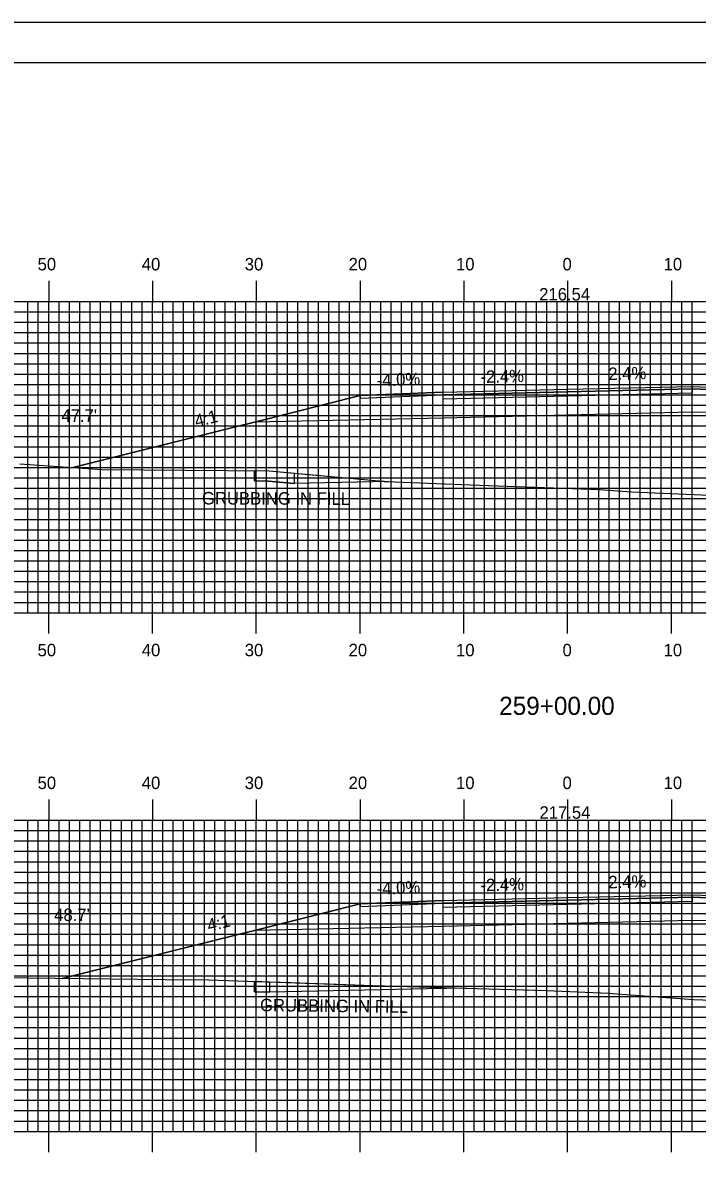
# Model space of a CAD drawing. Extents: x 1805471 to 1805814, y 442591 to 442811.
# Drawn here: x 1805584.2 to 1805649.2, y 442701.2 to 442810.5 of the extents above; entities that cross this region are included whole.
import ezdxf

# ---------------------------------------------------------------- set-up
doc = ezdxf.new("R2010")
doc.units = 0
for name, color, linetype in [('ANNOTATION', 7, 'Continuous'), ('BORDER', 7, 'Continuous'), ('D_Roadway_Centerline', 7, 'Continuous'), ('D_Roadway_Centerline_Text', 7, 'Continuous'), ('D_Roadway_Edge_Shoulder', 7, 'Continuous'), ('D_Roadway_Edge_TW', 7, 'Continuous'), ('D_Roadway_Pavement', 7, 'Continuous'), ('D_Roadway_SlopeLines', 7, 'Continuous'), ('D_Roadway_SubGrade', 7, 'Continuous'), ('D_Text_Standard', 7, 'Continuous'), ('GRUBBING IN FILL', 7, 'Continuous'), ('H_V ANNOTATION', 7, 'Continuous'), ('MAJOR', 7, 'Continuous'), ('MINOR', 7, 'Continuous'), ('PLOT BOUNDARY', 7, 'Continuous'), ('S_Roadway_Centerline', 7, 'Continuous')]:
    doc.layers.add(name, color=color, linetype=linetype)

msp = doc.modelspace()

# ---------------------------------------------------------------- linework, layer by layer
at = {"layer": 'BORDER'}
msp.add_lwpolyline([(1805487.11, 442596.67), (1805807.11, 442596.67), (1805807.11, 442806.67), (1805487.11, 442806.67)], close=True, dxfattribs=at)
at = {"layer": 'D_Roadway_Centerline'}
for points in [[(1805589.04, 442767.68), (1805604.71, 442771.6), (1805606.53, 442772.05), (1805616.71, 442774.6), (1805624.71, 442774.92), (1805636.71, 442775.21), (1805648.71, 442775.49), (1805656.71, 442775.17), (1805666.88, 442772.63), (1805668.71, 442772.17), (1805696.54, 442762.9)], [(1805588.01, 442718.42), (1805604.71, 442722.6), (1805606.53, 442723.05), (1805616.71, 442725.6), (1805624.71, 442725.92), (1805636.71, 442726.21), (1805648.71, 442726.49), (1805656.71, 442726.17), (1805666.88, 442723.63), (1805668.71, 442723.17), (1805693.01, 442715.07)]]:
    msp.add_lwpolyline(points, dxfattribs=at)
at = {"layer": 'D_Roadway_Edge_Shoulder'}
for points in [[(1805648.71, 442775.49), (1805656.71, 442775.17), (1805656.71, 442774.92), (1805648.71, 442775.24)], [(1805624.71, 442774.92), (1805616.71, 442774.6), (1805616.71, 442774.35), (1805624.71, 442774.67)], [(1805648.71, 442726.49), (1805656.71, 442726.17), (1805656.71, 442725.92), (1805648.71, 442726.24)], [(1805624.71, 442725.92), (1805616.71, 442725.6), (1805616.71, 442725.35), (1805624.71, 442725.67)]]:
    msp.add_lwpolyline(points, close=True, dxfattribs=at)
at = {"layer": 'D_Roadway_Edge_TW'}
for points in [[(1805624.71, 442774.67), (1805624.71, 442774.92), (1805636.71, 442775.21), (1805648.71, 442775.49), (1805648.71, 442775.24), (1805636.71, 442774.96)], [(1805624.71, 442725.67), (1805624.71, 442725.92), (1805636.71, 442726.21), (1805648.71, 442726.49), (1805648.71, 442726.24), (1805636.71, 442725.96)]]:
    msp.add_lwpolyline(points, close=True, dxfattribs=at)
at = {"layer": 'D_Roadway_Pavement'}
for points in [[(1805624.71, 442774.25), (1805624.71, 442774.67), (1805636.71, 442774.96), (1805648.71, 442775.24), (1805648.71, 442774.83), (1805636.71, 442774.54)], [(1805624.71, 442725.25), (1805624.71, 442725.67), (1805636.71, 442725.96), (1805648.71, 442726.24), (1805648.71, 442725.83), (1805636.71, 442725.54)]]:
    msp.add_lwpolyline(points, close=True, dxfattribs=at)
at = {"layer": 'D_Roadway_SlopeLines'}
for points in [[(1805616.71, 442774.6), (1805606.53, 442772.05), (1805604.71, 442771.6), (1805589.04, 442767.68)], [(1805616.71, 442725.6), (1805606.53, 442723.05), (1805604.71, 442722.6), (1805588.01, 442718.42)]]:
    msp.add_lwpolyline(points, dxfattribs=at)
at = {"layer": 'D_Roadway_SubGrade'}
for points in [[(1805624.71, 442772.42), (1805606.53, 442772.05), (1805616.71, 442774.6), (1805616.71, 442774.35), (1805624.71, 442774.67), (1805636.71, 442774.96), (1805648.71, 442775.24), (1805656.71, 442774.92), (1805656.71, 442775.17), (1805666.88, 442772.63), (1805648.71, 442772.99), (1805636.71, 442772.71)], [(1805624.71, 442723.42), (1805606.53, 442723.05), (1805616.71, 442725.6), (1805616.71, 442725.35), (1805624.71, 442725.67), (1805636.71, 442725.96), (1805648.71, 442726.24), (1805656.71, 442725.92), (1805656.71, 442726.17), (1805666.88, 442723.63), (1805648.71, 442723.99), (1805636.71, 442723.71)]]:
    msp.add_lwpolyline(points, close=True, dxfattribs=at)
at = {"layer": 'GRUBBING IN FILL'}
for p, q in [((1805606.53, 442767.37), (1805606.53, 442766.37)), ((1805606.53, 442767.37), (1805606.53, 442766.37)), ((1805610.37, 442767.13), (1805610.37, 442766.13)), ((1805610.37, 442767.13), (1805610.37, 442766.13)), ((1805606.53, 442718.14), (1805606.53, 442717.14)), ((1805606.53, 442718.14), (1805606.53, 442717.14)), ((1805608, 442718.08), (1805608, 442717.08)), ((1805608, 442718.08), (1805608, 442717.08))]:
    msp.add_line(p, q, dxfattribs=at)
for points in [[(1805606.53, 442767.37), (1805607.94, 442767.36), (1805610.37, 442767.13), (1805618.17, 442766.41), (1805619.44, 442766.31), (1805610.37, 442766.13), (1805607.89, 442766.36), (1805606.53, 442766.37)], [(1805606.53, 442767.37), (1805607.94, 442767.36), (1805610.37, 442767.13), (1805618.17, 442766.41), (1805619.44, 442766.31), (1805610.37, 442766.13), (1805607.89, 442766.36), (1805606.53, 442766.37)], [(1805606.53, 442718.14), (1805608, 442718.08), (1805610.05, 442718.01), (1805617.95, 442717.73), (1805626.94, 442717.48), (1805623.18, 442717.4), (1805615.64, 442717.24), (1805611.1, 442717.15), (1805608, 442717.08), (1805606.53, 442717.13)], [(1805606.53, 442718.14), (1805608, 442718.08), (1805610.05, 442718.01), (1805617.95, 442717.73), (1805626.94, 442717.48), (1805623.18, 442717.4), (1805615.64, 442717.24), (1805611.1, 442717.15), (1805608, 442717.08), (1805606.53, 442717.13)]]:
    msp.add_lwpolyline(points, close=True, dxfattribs=at)
for points in [[(1805606.53, 442766.37), (1805607.89, 442766.36), (1805610.37, 442766.13)], [(1805606.53, 442766.37), (1805607.89, 442766.36), (1805610.37, 442766.13)], [(1805606.53, 442717.13), (1805607.99, 442717.08)], [(1805606.53, 442717.13), (1805607.99, 442717.08)]]:
    msp.add_lwpolyline(points, dxfattribs=at)
at = {"layer": 'MAJOR'}
for p, q in [((1805586.71, 442785.67), (1805586.71, 442783.67)), ((1805596.71, 442785.67), (1805596.71, 442783.67)), ((1805606.71, 442785.67), (1805606.71, 442783.67)), ((1805616.71, 442785.67), (1805616.71, 442783.67)), ((1805626.71, 442785.67), (1805626.71, 442783.67)), ((1805636.71, 442785.67), (1805636.71, 442783.67)), ((1805646.71, 442785.67), (1805646.71, 442783.67)), ((1805496.71, 442783.67), (1805776.71, 442783.67)), ((1805496.71, 442783.67), (1805776.71, 442783.67)), ((1805586.71, 442753.67), (1805586.71, 442783.67)), ((1805596.71, 442753.67), (1805596.71, 442783.67)), ((1805606.71, 442753.67), (1805606.71, 442783.67)), ((1805616.71, 442753.67), (1805616.71, 442783.67)), ((1805626.71, 442753.67), (1805626.71, 442783.67)), ((1805636.71, 442753.67), (1805636.71, 442783.67)), ((1805646.71, 442753.67), (1805646.71, 442783.67)), ((1805496.71, 442778.67), (1805776.71, 442778.67)), ((1805496.71, 442773.67), (1805776.71, 442773.67)), ((1805496.71, 442768.67), (1805776.71, 442768.67)), ((1805496.71, 442763.67), (1805776.71, 442763.67)), ((1805496.71, 442758.67), (1805776.71, 442758.67)), ((1805496.71, 442753.67), (1805776.71, 442753.67)), ((1805496.71, 442753.67), (1805776.71, 442753.67)), ((1805586.71, 442751.66), (1805586.71, 442753.67)), ((1805596.71, 442751.66), (1805596.71, 442753.67)), ((1805606.71, 442751.66), (1805606.71, 442753.67)), ((1805616.71, 442751.66), (1805616.71, 442753.67)), ((1805626.71, 442751.66), (1805626.71, 442753.67)), ((1805636.71, 442751.66), (1805636.71, 442753.67)), ((1805646.71, 442751.66), (1805646.71, 442753.67)), ((1805586.71, 442735.67), (1805586.71, 442733.67)), ((1805596.71, 442735.67), (1805596.71, 442733.67)), ((1805606.71, 442735.67), (1805606.71, 442733.67)), ((1805616.71, 442735.67), (1805616.71, 442733.67)), ((1805626.71, 442735.67), (1805626.71, 442733.67)), ((1805636.71, 442735.67), (1805636.71, 442733.67)), ((1805646.71, 442735.67), (1805646.71, 442733.67)), ((1805496.71, 442733.67), (1805776.71, 442733.67)), ((1805496.71, 442733.67), (1805776.71, 442733.67)), ((1805586.71, 442703.67), (1805586.71, 442733.67)), ((1805596.71, 442703.67), (1805596.71, 442733.67)), ((1805606.71, 442703.67), (1805606.71, 442733.67)), ((1805616.71, 442703.67), (1805616.71, 442733.67)), ((1805626.71, 442703.67), (1805626.71, 442733.67)), ((1805636.71, 442703.67), (1805636.71, 442733.67)), ((1805646.71, 442703.67), (1805646.71, 442733.67)), ((1805496.71, 442728.67), (1805776.71, 442728.67)), ((1805496.71, 442723.67), (1805776.71, 442723.67)), ((1805496.71, 442718.67), (1805776.71, 442718.67)), ((1805496.71, 442713.67), (1805776.71, 442713.67)), ((1805496.71, 442708.67), (1805776.71, 442708.67)), ((1805496.71, 442703.67), (1805776.71, 442703.67)), ((1805496.71, 442703.67), (1805776.71, 442703.67)), ((1805586.71, 442701.66), (1805586.71, 442703.67)), ((1805596.71, 442701.66), (1805596.71, 442703.67)), ((1805606.71, 442701.66), (1805606.71, 442703.67)), ((1805616.71, 442701.66), (1805616.71, 442703.67)), ((1805626.71, 442701.66), (1805626.71, 442703.67)), ((1805636.71, 442701.66), (1805636.71, 442703.67)), ((1805646.71, 442701.66), (1805646.71, 442703.67))]:
    msp.add_line(p, q, dxfattribs=at)
at = {"layer": 'MINOR'}
for p, q in [((1805584.71, 442753.67), (1805584.71, 442783.67)), ((1805585.71, 442753.67), (1805585.71, 442783.67)), ((1805587.71, 442753.67), (1805587.71, 442783.67)), ((1805588.71, 442753.67), (1805588.71, 442783.67)), ((1805589.71, 442753.67), (1805589.71, 442783.67)), ((1805590.71, 442753.67), (1805590.71, 442783.67)), ((1805591.71, 442753.67), (1805591.71, 442783.67)), ((1805592.71, 442753.67), (1805592.71, 442783.67)), ((1805593.71, 442753.67), (1805593.71, 442783.67)), ((1805594.71, 442753.67), (1805594.71, 442783.67)), ((1805595.71, 442753.67), (1805595.71, 442783.67)), ((1805597.71, 442753.67), (1805597.71, 442783.67)), ((1805598.71, 442753.67), (1805598.71, 442783.67)), ((1805599.71, 442753.67), (1805599.71, 442783.67)), ((1805600.71, 442753.67), (1805600.71, 442783.67)), ((1805601.71, 442753.67), (1805601.71, 442783.67)), ((1805602.71, 442753.67), (1805602.71, 442783.67)), ((1805603.71, 442753.67), (1805603.71, 442783.67)), ((1805604.71, 442753.67), (1805604.71, 442783.67)), ((1805605.71, 442753.67), (1805605.71, 442783.67)), ((1805607.71, 442753.67), (1805607.71, 442783.67)), ((1805608.71, 442753.67), (1805608.71, 442783.67)), ((1805609.71, 442753.67), (1805609.71, 442783.67)), ((1805610.71, 442753.67), (1805610.71, 442783.67)), ((1805611.71, 442753.67), (1805611.71, 442783.67)), ((1805612.71, 442753.67), (1805612.71, 442783.67)), ((1805613.71, 442753.67), (1805613.71, 442783.67)), ((1805614.71, 442753.67), (1805614.71, 442783.67)), ((1805615.71, 442753.67), (1805615.71, 442783.67)), ((1805617.71, 442753.67), (1805617.71, 442783.67)), ((1805618.71, 442753.67), (1805618.71, 442783.67)), ((1805619.71, 442753.67), (1805619.71, 442783.67)), ((1805620.71, 442753.67), (1805620.71, 442783.67)), ((1805621.71, 442753.67), (1805621.71, 442783.67)), ((1805622.71, 442753.67), (1805622.71, 442783.67)), ((1805623.71, 442753.67), (1805623.71, 442783.67)), ((1805624.71, 442753.67), (1805624.71, 442783.67)), ((1805625.71, 442753.67), (1805625.71, 442783.67)), ((1805627.71, 442753.67), (1805627.71, 442783.67)), ((1805628.71, 442753.67), (1805628.71, 442783.67)), ((1805629.71, 442753.67), (1805629.71, 442783.67)), ((1805630.71, 442753.67), (1805630.71, 442783.67)), ((1805631.71, 442753.67), (1805631.71, 442783.67)), ((1805632.71, 442753.67), (1805632.71, 442783.67)), ((1805633.71, 442753.67), (1805633.71, 442783.67)), ((1805634.71, 442753.67), (1805634.71, 442783.67)), ((1805635.71, 442753.67), (1805635.71, 442783.67)), ((1805637.71, 442753.67), (1805637.71, 442783.67)), ((1805638.71, 442753.67), (1805638.71, 442783.67)), ((1805639.71, 442753.67), (1805639.71, 442783.67)), ((1805640.71, 442753.67), (1805640.71, 442783.67)), ((1805641.71, 442753.67), (1805641.71, 442783.67)), ((1805642.71, 442753.67), (1805642.71, 442783.67)), ((1805643.71, 442753.67), (1805643.71, 442783.67)), ((1805644.71, 442753.67), (1805644.71, 442783.67)), ((1805645.71, 442753.67), (1805645.71, 442783.67)), ((1805647.71, 442753.67), (1805647.71, 442783.67)), ((1805648.71, 442753.67), (1805648.71, 442783.67)), ((1805496.71, 442782.67), (1805776.71, 442782.67)), ((1805496.71, 442781.67), (1805776.71, 442781.67)), ((1805496.71, 442780.67), (1805776.71, 442780.67)), ((1805496.71, 442779.67), (1805776.71, 442779.67)), ((1805496.71, 442777.67), (1805776.71, 442777.67)), ((1805496.71, 442776.67), (1805776.71, 442776.67)), ((1805496.71, 442775.67), (1805776.71, 442775.67)), ((1805496.71, 442774.67), (1805776.71, 442774.67)), ((1805496.71, 442772.67), (1805776.71, 442772.67)), ((1805496.71, 442771.67), (1805776.71, 442771.67)), ((1805496.71, 442770.67), (1805776.71, 442770.67)), ((1805496.71, 442769.67), (1805776.71, 442769.67)), ((1805496.71, 442767.67), (1805776.71, 442767.67)), ((1805496.71, 442766.67), (1805776.71, 442766.67)), ((1805496.71, 442765.67), (1805776.71, 442765.67)), ((1805496.71, 442764.67), (1805776.71, 442764.67)), ((1805496.71, 442762.67), (1805776.71, 442762.67)), ((1805496.71, 442761.67), (1805776.71, 442761.67)), ((1805496.71, 442760.67), (1805776.71, 442760.67)), ((1805496.71, 442759.67), (1805776.71, 442759.67)), ((1805496.71, 442757.67), (1805776.71, 442757.67)), ((1805496.71, 442756.67), (1805776.71, 442756.67)), ((1805496.71, 442755.67), (1805776.71, 442755.67)), ((1805496.71, 442754.67), (1805776.71, 442754.67)), ((1805584.71, 442703.67), (1805584.71, 442733.67)), ((1805585.71, 442703.67), (1805585.71, 442733.67)), ((1805587.71, 442703.67), (1805587.71, 442733.67)), ((1805588.71, 442703.67), (1805588.71, 442733.67)), ((1805589.71, 442703.67), (1805589.71, 442733.67)), ((1805590.71, 442703.67), (1805590.71, 442733.67)), ((1805591.71, 442703.67), (1805591.71, 442733.67)), ((1805592.71, 442703.67), (1805592.71, 442733.67)), ((1805593.71, 442703.67), (1805593.71, 442733.67)), ((1805594.71, 442703.67), (1805594.71, 442733.67)), ((1805595.71, 442703.67), (1805595.71, 442733.67)), ((1805597.71, 442703.67), (1805597.71, 442733.67)), ((1805598.71, 442703.67), (1805598.71, 442733.67)), ((1805599.71, 442703.67), (1805599.71, 442733.67)), ((1805600.71, 442703.67), (1805600.71, 442733.67)), ((1805601.71, 442703.67), (1805601.71, 442733.67)), ((1805602.71, 442703.67), (1805602.71, 442733.67)), ((1805603.71, 442703.67), (1805603.71, 442733.67)), ((1805604.71, 442703.67), (1805604.71, 442733.67)), ((1805605.71, 442703.67), (1805605.71, 442733.67)), ((1805607.71, 442703.67), (1805607.71, 442733.67)), ((1805608.71, 442703.67), (1805608.71, 442733.67)), ((1805609.71, 442703.67), (1805609.71, 442733.67)), ((1805610.71, 442703.67), (1805610.71, 442733.67)), ((1805611.71, 442703.67), (1805611.71, 442733.67)), ((1805612.71, 442703.67), (1805612.71, 442733.67)), ((1805613.71, 442703.67), (1805613.71, 442733.67)), ((1805614.71, 442703.67), (1805614.71, 442733.67)), ((1805615.71, 442703.67), (1805615.71, 442733.67)), ((1805617.71, 442703.67), (1805617.71, 442733.67)), ((1805618.71, 442703.67), (1805618.71, 442733.67)), ((1805619.71, 442703.67), (1805619.71, 442733.67)), ((1805620.71, 442703.67), (1805620.71, 442733.67)), ((1805621.71, 442703.67), (1805621.71, 442733.67)), ((1805622.71, 442703.67), (1805622.71, 442733.67)), ((1805623.71, 442703.67), (1805623.71, 442733.67)), ((1805624.71, 442703.67), (1805624.71, 442733.67)), ((1805625.71, 442703.67), (1805625.71, 442733.67)), ((1805627.71, 442703.67), (1805627.71, 442733.67)), ((1805628.71, 442703.67), (1805628.71, 442733.67)), ((1805629.71, 442703.67), (1805629.71, 442733.67)), ((1805630.71, 442703.67), (1805630.71, 442733.67)), ((1805631.71, 442703.67), (1805631.71, 442733.67)), ((1805632.71, 442703.67), (1805632.71, 442733.67)), ((1805633.71, 442703.67), (1805633.71, 442733.67)), ((1805634.71, 442703.67), (1805634.71, 442733.67)), ((1805635.71, 442703.67), (1805635.71, 442733.67)), ((1805637.71, 442703.67), (1805637.71, 442733.67)), ((1805638.71, 442703.67), (1805638.71, 442733.67)), ((1805639.71, 442703.67), (1805639.71, 442733.67)), ((1805640.71, 442703.67), (1805640.71, 442733.67)), ((1805641.71, 442703.67), (1805641.71, 442733.67)), ((1805642.71, 442703.67), (1805642.71, 442733.67)), ((1805643.71, 442703.67), (1805643.71, 442733.67)), ((1805644.71, 442703.67), (1805644.71, 442733.67)), ((1805645.71, 442703.67), (1805645.71, 442733.67)), ((1805647.71, 442703.67), (1805647.71, 442733.67)), ((1805648.71, 442703.67), (1805648.71, 442733.67)), ((1805496.71, 442732.67), (1805776.71, 442732.67)), ((1805496.71, 442731.67), (1805776.71, 442731.67)), ((1805496.71, 442730.67), (1805776.71, 442730.67)), ((1805496.71, 442729.67), (1805776.71, 442729.67)), ((1805496.71, 442727.67), (1805776.71, 442727.67)), ((1805496.71, 442726.67), (1805776.71, 442726.67)), ((1805496.71, 442725.67), (1805776.71, 442725.67)), ((1805496.71, 442724.67), (1805776.71, 442724.67)), ((1805496.71, 442722.67), (1805776.71, 442722.67)), ((1805496.71, 442721.67), (1805776.71, 442721.67)), ((1805496.71, 442720.67), (1805776.71, 442720.67)), ((1805496.71, 442719.67), (1805776.71, 442719.67)), ((1805496.71, 442717.67), (1805776.71, 442717.67)), ((1805496.71, 442716.67), (1805776.71, 442716.67)), ((1805496.71, 442715.67), (1805776.71, 442715.67)), ((1805496.71, 442714.67), (1805776.71, 442714.67)), ((1805496.71, 442712.67), (1805776.71, 442712.67)), ((1805496.71, 442711.67), (1805776.71, 442711.67)), ((1805496.71, 442710.67), (1805776.71, 442710.67)), ((1805496.71, 442709.67), (1805776.71, 442709.67)), ((1805496.71, 442707.67), (1805776.71, 442707.67)), ((1805496.71, 442706.67), (1805776.71, 442706.67)), ((1805496.71, 442705.67), (1805776.71, 442705.67)), ((1805496.71, 442704.67), (1805776.71, 442704.67))]:
    msp.add_line(p, q, dxfattribs=at)
at = {"layer": 'PLOT BOUNDARY'}
msp.add_lwpolyline([(1805470.92, 442590.55), (1805810.92, 442590.55), (1805810.92, 442810.55), (1805470.92, 442810.55)], close=True, dxfattribs=at)
at = {"layer": 'S_Roadway_Centerline'}
for points in [[(1805583.93, 442768.03), (1805591.82, 442767.49), (1805607.94, 442767.36), (1805618.17, 442766.41), (1805619.05, 442766.33), (1805620.02, 442766.29), (1805627.31, 442765.99), (1805639.82, 442765.54), (1805642.86, 442765.33), (1805654.18, 442764.85), (1805663.09, 442764.43), (1805665.75, 442764.29), (1805668.86, 442764.13), (1805682.7, 442763.34), (1805694.58, 442763.03), (1805705.07, 442762.34)], [(1805579.42, 442718.53), (1805597.92, 442718.31), (1805602.14, 442718.29), (1805617.95, 442717.73), (1805634.67, 442717.26), (1805640.65, 442716.98), (1805648.85, 442716.38), (1805660.37, 442715.96), (1805661.69, 442715.93), (1805662.57, 442715.89), (1805671.48, 442715.56), (1805682.02, 442715.18), (1805683.18, 442715.16), (1805684.66, 442715.15), (1805696.25, 442715.04), (1805705.33, 442714.54)]]:
    msp.add_lwpolyline(points, dxfattribs=at)

# ---------------------------------------------------------------- texts
at = {"layer": 'ANNOTATION'}
for s, rotation, p in [('-4.0%', 2.2906, (1805618.34, 442775.47)), ('-2.4%', 1.3748, (1805628.33, 442775.81)), ('2.4%', 1.3748, (1805640.65, 442776.1)), ('4:1', 14.0362, (1805600.94, 442771.54)), ('2.4%', 1.3748, (1805640.65, 442727.1)), ('-4.0%', 2.2906, (1805618.34, 442726.47)), ('-2.4%', 1.3748, (1805628.33, 442726.81)), ('4:1', 14.0362, (1805602.14, 442722.91))]:
    msp.add_text(s, height=1.2, rotation=rotation, dxfattribs=at).set_placement(p)
at = {"layer": 'D_Roadway_Centerline'}
for s, p in [('C', (1805636.7, 442775.21)), ('L', (1805636.71, 442775.2)), ('C', (1805636.7, 442726.21)), ('L', (1805636.71, 442726.2))]:
    msp.add_text(s, height=0.0146, dxfattribs=at).set_placement(p)
at = {"layer": 'D_Roadway_Centerline_Text'}
for s, p in [('216.54', (1805633.97, 442783.77)), ('217.54', (1805634, 442733.81))]:
    msp.add_text(s, height=1.2, dxfattribs=at).set_placement(p)
at = {"layer": 'D_Text_Standard'}
for s, p in [("47.7'", (1805587.94, 442772.07)), ("48.7'", (1805587.24, 442723.95))]:
    msp.add_text(s, height=1.2, dxfattribs=at).set_placement(p)
at = {"layer": 'GRUBBING IN FILL'}
for rotation, p in [(359.8053, (1805601.48, 442764.11)), (359.3278, (1805607.07, 442715.26))]:
    msp.add_text('GRUBBING IN FILL', height=1.2, rotation=rotation, dxfattribs=at).set_placement(p)
at = {"layer": 'H_V ANNOTATION'}
for s, height, p in [('50', 1.2, (1805585.64, 442786.67)), ('40', 1.2, (1805595.68, 442786.67)), ('30', 1.2, (1805605.6, 442786.67)), ('20', 1.2, (1805615.61, 442786.67)), ('10', 1.2, (1805625.96, 442786.67)), ('0', 1.2, (1805636.22, 442786.67)), ('10', 1.2, (1805645.96, 442786.67)), ('50', 1.2, (1805585.64, 442749.47)), ('40', 1.2, (1805595.68, 442749.47)), ('30', 1.2, (1805605.6, 442749.47)), ('20', 1.2, (1805615.61, 442749.47)), ('10', 1.2, (1805625.96, 442749.47)), ('0', 1.2, (1805636.22, 442749.47)), ('10', 1.2, (1805645.96, 442749.47)), ('259+00.00', 1.75, (1805630.12, 442743.82)), ('50', 1.2, (1805585.64, 442736.67)), ('40', 1.2, (1805595.68, 442736.67)), ('30', 1.2, (1805605.6, 442736.67)), ('20', 1.2, (1805615.61, 442736.67)), ('10', 1.2, (1805625.96, 442736.67)), ('0', 1.2, (1805636.22, 442736.67)), ('10', 1.2, (1805645.96, 442736.67))]:
    msp.add_text(s, height=height, dxfattribs=at).set_placement(p)

doc.saveas('drawing.dxf')
